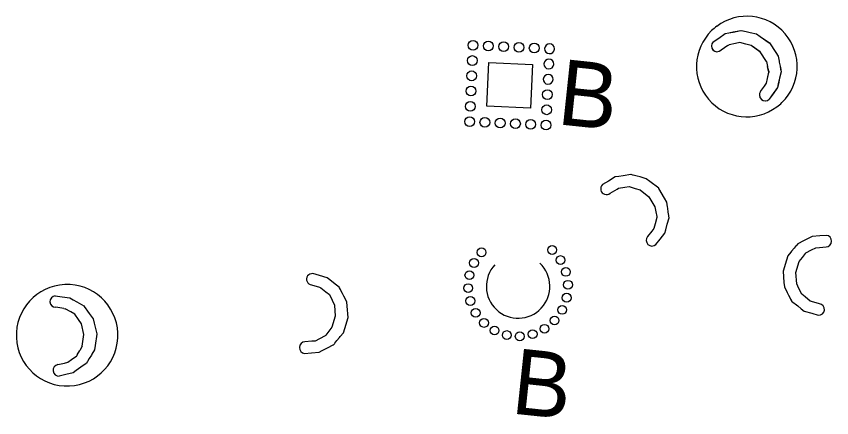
# Model space of a CAD drawing. Extents: x 2283629 to 2286552, y 529718 to 531440.
# Drawn here: x 2285323.2 to 2285509.6, y 530057 to 530148.9 of the extents above; entities that cross this region are included whole.
import ezdxf

# ---------------------------------------------------------------- set-up
doc = ezdxf.new("R2010")
doc.units = 0
for name, color, linetype in [('Draft_Corridor_Graphics_Design', 7, 'Continuous'), ('Draft_Corridor_Point_Control', 7, 'Continuous'), ('P_NCDOT_Terrain_Model_Contour_Major', 7, 'Continuous'), ('P_NCDOT_Terrain_Model_Triangles', 7, 'Continuous'), ('P_NCDOT_Terrain_Triangle_Vertices', 7, 'Continuous'), ('P_RDY_TC_Pvmt_Asphalt_Base_Course_Wedge', 7, 'Continuous'), ('P_RDY_TC_Pvmt_Asphalt_Surface_Course_Wedge', 7, 'Continuous')]:
    doc.layers.add(name, color=color, linetype=linetype)

msp = doc.modelspace()

# ---------------------------------------------------------------- linework, layer by layer
at = {"layer": 'Draft_Corridor_Point_Control'}
for p, q in [((2285446.23, 530141.4), (2285446.24, 530141.5)), ((2285446.08, 530137.91), (2285446.08, 530138)), ((2285445.92, 530134.42), (2285445.92, 530134.49))]:
    msp.add_line(p, q, dxfattribs=at)
msp.add_lwpolyline([(2285431.21, 530138.37), (2285441.2, 530137.91), (2285440.75, 530127.92), (2285430.76, 530128.39)], close=True, dxfattribs=at)
for centre in [(2285427.63, 530142.3), (2285431.13, 530142.14), (2285434.63, 530141.98), (2285438.12, 530141.82), (2285441.62, 530141.66), (2285427.47, 530138.8), (2285427.31, 530135.3), (2285427.16, 530131.81), (2285444.64, 530131.01), (2285427, 530128.31), (2285444.48, 530127.52), (2285426.84, 530124.81), (2285430.33, 530124.65), (2285433.83, 530124.5), (2285437.33, 530124.34), (2285440.82, 530124.18), (2285444.32, 530124.02)]:
    msp.add_circle(centre, 1.12, dxfattribs=at)
for centre, start, end in [((2285445.12, 530141.5), 359.9118, 354.8889), ((2285444.96, 530138), 359.5752, 355.2254), ((2285444.8, 530134.51), 359.1761, 355.6245)]:
    msp.add_arc(centre, 1.12, start, end, dxfattribs=at)
at = {"layer": 'P_NCDOT_Terrain_Model_Contour_Major'}
for p, q in [((2285485.88, 530142.23), (2285484.33, 530141.2)), ((2285485.89, 530142.22), (2285484.34, 530141.19)), ((2285485.88, 530142.23), (2285486.16, 530142.41)), ((2285485.89, 530142.22), (2285486.17, 530142.4)), ((2285487.61, 530142.7), (2285486.16, 530142.41)), ((2285487.62, 530142.7), (2285486.17, 530142.4)), ((2285488.62, 530142.91), (2285487.61, 530142.7)), ((2285488.63, 530142.9), (2285487.62, 530142.7)), ((2285490.02, 530142.56), (2285488.62, 530142.91)), ((2285490.03, 530142.55), (2285488.63, 530142.9)), ((2285491.19, 530142.27), (2285490.02, 530142.56)), ((2285491.2, 530142.26), (2285490.03, 530142.55)), ((2285493.24, 530140.77), (2285491.19, 530142.27)), ((2285493.25, 530140.77), (2285491.2, 530142.26)), ((2285493.24, 530140.77), (2285493.25, 530140.77)), ((2285493.25, 530140.77), (2285493.26, 530140.76)), ((2285494.73, 530138.59), (2285493.25, 530140.77)), ((2285494.74, 530138.58), (2285493.26, 530140.76)), ((2285494.73, 530138.59), (2285494.98, 530137.43)), ((2285494.74, 530138.58), (2285494.99, 530137.42)), ((2285494.96, 530134.69), (2285495.27, 530136.11)), ((2285494.97, 530134.68), (2285495.28, 530136.1)), ((2285495.22, 530136.34), (2285494.98, 530137.43)), ((2285495.23, 530136.33), (2285494.99, 530137.42)), ((2285495.22, 530136.34), (2285495.27, 530136.11)), ((2285495.23, 530136.33), (2285495.28, 530136.1)), ((2285494.73, 530133.61), (2285494.96, 530134.69)), ((2285494.73, 530133.61), (2285494.97, 530134.68)), ((2285493.36, 530131.71), (2285494.27, 530132.97)), ((2285493.37, 530131.7), (2285494.28, 530132.96)), ((2285494.27, 530132.97), (2285494.73, 530133.61)), ((2285494.28, 530132.96), (2285494.73, 530133.61))]:
    msp.add_line(p, q, dxfattribs=at)
for points in [[(2285482.52, 530143.06), (2285483.81, 530143.94), (2285485.31, 530144.97), (2285486.12, 530145.14), (2285487.11, 530145.34), (2285488.87, 530145.7), (2285488.91, 530145.69), (2285489.34, 530145.6), (2285489.42, 530145.58), (2285490.35, 530145.37), (2285491, 530145.23), (2285492.43, 530144.91), (2285493.28, 530144.31), (2285495.37, 530142.85), (2285495.38, 530142.84), (2285496.83, 530140.64), (2285497.4, 530139.78), (2285497.61, 530138.67), (2285497.66, 530138.43), (2285497.83, 530137.49), (2285497.97, 530136.77), (2285498, 530136.6), (2285498.07, 530136.24), (2285498.07, 530136.23), (2285497.73, 530134.76), (2285497.43, 530133.45), (2285497.25, 530132.66), (2285496.24, 530131.22), (2285495.36, 530129.95)], [(2285482.53, 530143.05), (2285483.81, 530143.93), (2285485.31, 530144.96), (2285486.13, 530145.13), (2285487.12, 530145.33), (2285488.88, 530145.69), (2285488.92, 530145.68), (2285489.35, 530145.59), (2285489.42, 530145.57), (2285490.36, 530145.36), (2285491.01, 530145.22), (2285492.44, 530144.9), (2285493.29, 530144.3), (2285495.38, 530142.84), (2285495.39, 530142.83), (2285496.84, 530140.63), (2285497.41, 530139.77), (2285497.62, 530138.66), (2285497.66, 530138.43), (2285497.84, 530137.48), (2285497.98, 530136.76), (2285498.01, 530136.59), (2285498.08, 530136.23), (2285498.08, 530136.23), (2285497.74, 530134.75), (2285497.44, 530133.45), (2285497.25, 530132.66), (2285496.25, 530131.21), (2285495.37, 530129.94)]]:
    msp.add_lwpolyline(points, dxfattribs=at)
for centre, radius, start, end in [((2285490.25, 530137.43), 11.5, 314.2425, 126.889), ((2285490.21, 530137.41), 11.5, 134.2425, 306.6479), ((2285490.21, 530137.41), 11.5, 126.6479, 134.2425), ((2285483.42, 530142.13), 1.3, 134.2425, 314.2425), ((2285483.43, 530142.12), 1.3, 134.2425, 314.2425), ((2285494.43, 530130.91), 1.33, 143.1299, 314.2425), ((2285494.44, 530130.9), 1.33, 143.1299, 314.2425), ((2285490.25, 530137.43), 11.5, 306.4067, 314.2425)]:
    msp.add_arc(centre, radius, start, end, dxfattribs=at)
at = {"layer": 'P_NCDOT_Terrain_Model_Triangles'}
for p, q in [((2285460.57, 530109.39), (2285460.86, 530109.56)), ((2285467.85, 530107.58), (2285467.86, 530107.57)), ((2285469.23, 530105.33), (2285469.43, 530104.16)), ((2285469.62, 530103.06), (2285469.65, 530102.83))]:
    msp.add_line(p, q, dxfattribs=at)
for points in [[(2285469.45, 530096.67), (2285470.39, 530097.9), (2285471.46, 530099.29), (2285471.68, 530100.07), (2285472.05, 530101.36), (2285472.46, 530102.82), (2285472.46, 530102.82), (2285472.4, 530103.19), (2285472.38, 530103.36), (2285472.28, 530104.08), (2285472.15, 530105.03), (2285472.12, 530105.27), (2285471.96, 530106.39), (2285471.43, 530107.27), (2285470.09, 530109.54), (2285470.08, 530109.55), (2285468.07, 530111.11), (2285467.24, 530111.75), (2285465.83, 530112.14), (2285465.19, 530112.32), (2285464.27, 530112.57), (2285464.19, 530112.59), (2285463.77, 530112.71), (2285463.73, 530112.72), (2285461.96, 530112.44), (2285460.96, 530112.28), (2285460.13, 530112.15), (2285458.58, 530111.2), (2285457.25, 530110.39)], [(2285458.97, 530108.44), (2285460.57, 530109.39), (2285460.86, 530109.56), (2285462.32, 530109.78), (2285463.34, 530109.94), (2285464.72, 530109.53), (2285465.88, 530109.18), (2285467.85, 530107.58), (2285467.86, 530107.57), (2285469.23, 530105.33), (2285469.43, 530104.16), (2285469.62, 530103.06), (2285469.65, 530102.83), (2285469.28, 530101.43), (2285468.99, 530100.36), (2285468.5, 530099.74), (2285467.54, 530098.52), (2285467.54, 530098.52)]]:
    msp.add_lwpolyline(points, dxfattribs=at)
for centre, radius, start in [((2285458.11, 530109.41), 1.3, 131.4705), ((2285468.56, 530097.67), 1.33, 140.3579)]:
    msp.add_arc(centre, radius, start, 311.4705, dxfattribs=at)
at = {"layer": 'P_NCDOT_Terrain_Triangle_Vertices'}
for p, q in [((2285334.07, 530082.04), (2285332.23, 530082.3)), ((2285334.07, 530082.04), (2285334.4, 530081.99)), ((2285335.68, 530081.25), (2285334.4, 530081.99)), ((2285336.57, 530080.73), (2285335.68, 530081.25)), ((2285337.39, 530079.54), (2285336.57, 530080.73)), ((2285338.07, 530078.55), (2285337.39, 530079.54)), ((2285338.61, 530076.06), (2285338.07, 530078.55)), ((2285338.27, 530073.44), (2285338.61, 530076.05)), ((2285338.61, 530076.06), (2285338.61, 530076.05)), ((2285337.14, 530071.44), (2285337.69, 530072.4)), ((2285338.27, 530073.44), (2285337.69, 530072.4)), ((2285335.85, 530070.38), (2285337.03, 530071.23)), ((2285337.14, 530071.44), (2285337.03, 530071.23)), ((2285332.68, 530069.21), (2285334.19, 530069.55)), ((2285334.19, 530069.55), (2285334.96, 530069.73)), ((2285334.96, 530069.73), (2285335.85, 530070.38))]:
    msp.add_line(p, q, dxfattribs=at)
msp.add_lwpolyline([(2285332.11, 530084.9), (2285333.66, 530084.7), (2285335.46, 530084.47), (2285336.19, 530084.05), (2285337.06, 530083.55), (2285338.62, 530082.65), (2285338.64, 530082.62), (2285338.9, 530082.26), (2285338.94, 530082.2), (2285339.5, 530081.42), (2285339.89, 530080.88), (2285340.75, 530079.69), (2285340.99, 530078.68), (2285341.58, 530076.2), (2285341.58, 530076.19), (2285341.2, 530073.58), (2285341.06, 530072.56), (2285340.47, 530071.59), (2285340.35, 530071.38), (2285339.86, 530070.56), (2285339.48, 530069.93), (2285339.39, 530069.79), (2285339.21, 530069.47), (2285339.2, 530069.46), (2285337.97, 530068.59), (2285336.87, 530067.81), (2285336.21, 530067.34), (2285334.51, 530066.93), (2285333, 530066.57)], dxfattribs=at)
for centre, radius, start, end in [((2285334.81, 530075.91), 11.62, 92.6069, 182.6069), ((2285334.81, 530075.91), 11.62, 2.6069, 92.6069), ((2285332.17, 530083.6), 1.3, 92.6069, 272.6069), ((2285334.81, 530075.91), 11.62, 272.6069, 2.6069), ((2285334.81, 530075.91), 11.62, 182.6069, 272.6069), ((2285332.94, 530067.9), 1.33, 101.4943, 272.6069)]:
    msp.add_arc(centre, radius, start, end, dxfattribs=at)
at = {"layer": 'P_RDY_TC_Pvmt_Asphalt_Base_Course_Wedge'}
for p, q in [((2285503.62, 530094.59), (2285503.76, 530094.78)), ((2285502.2, 530092.78), (2285502.93, 530093.72)), ((2285501.47, 530090.24), (2285501.47, 530090.25)), ((2285392.51, 530086.89), (2285392.82, 530086.79)), ((2285505.05, 530083.65), (2285504.74, 530083.74)), ((2285396.09, 530080.3), (2285396.09, 530080.29)), ((2285395.36, 530077.76), (2285394.63, 530076.82)), ((2285393.94, 530075.94), (2285393.8, 530075.76))]:
    msp.add_line(p, q, dxfattribs=at)
for points in [[(2285508.44, 530098.78), (2285506.9, 530098.65), (2285505.15, 530098.5), (2285504.43, 530098.13), (2285503.23, 530097.53), (2285501.88, 530096.85), (2285501.87, 530096.85), (2285501.64, 530096.56), (2285501.53, 530096.43), (2285501.07, 530095.87), (2285500.45, 530095.13), (2285500.3, 530094.94), (2285499.58, 530094.07), (2285499.28, 530093.09), (2285498.52, 530090.56), (2285498.52, 530090.55), (2285498.72, 530088.01), (2285498.81, 530086.97), (2285499.48, 530085.67), (2285499.78, 530085.07), (2285500.22, 530084.22), (2285500.25, 530084.16), (2285500.45, 530083.76), (2285500.47, 530083.73), (2285501.87, 530082.61), (2285502.66, 530081.97), (2285503.32, 530081.45), (2285505.06, 530080.95), (2285506.56, 530080.53)], [(2285506.84, 530083.11), (2285505.05, 530083.65), (2285504.74, 530083.74), (2285503.58, 530084.67), (2285502.78, 530085.32), (2285502.15, 530086.62), (2285501.63, 530087.7), (2285501.47, 530090.24), (2285501.47, 530090.25), (2285502.2, 530092.78), (2285502.93, 530093.72), (2285503.62, 530094.59), (2285503.76, 530094.78), (2285505.05, 530095.45), (2285506.03, 530095.95), (2285506.82, 530096.01), (2285508.37, 530096.12), (2285508.37, 530096.12)], [(2285389.12, 530071.75), (2285390.66, 530071.89), (2285392.41, 530072.04), (2285393.13, 530072.4), (2285394.33, 530073.01), (2285395.68, 530073.69), (2285395.69, 530073.69), (2285395.92, 530073.97), (2285396.03, 530074.11), (2285396.5, 530074.67), (2285397.11, 530075.41), (2285397.26, 530075.59), (2285397.98, 530076.46), (2285398.28, 530077.45), (2285399.04, 530079.97), (2285399.04, 530079.99), (2285398.84, 530082.53), (2285398.75, 530083.56), (2285398.08, 530084.87), (2285397.78, 530085.46), (2285397.34, 530086.31), (2285397.31, 530086.38), (2285397.11, 530086.77), (2285397.09, 530086.81), (2285395.69, 530087.93), (2285394.9, 530088.56), (2285394.24, 530089.08), (2285392.5, 530089.58), (2285391, 530090.01)], [(2285390.72, 530087.43), (2285392.51, 530086.89), (2285392.82, 530086.79), (2285393.98, 530085.86), (2285394.78, 530085.22), (2285395.41, 530083.92), (2285395.93, 530082.83), (2285396.09, 530080.3), (2285396.09, 530080.29), (2285395.36, 530077.76), (2285394.63, 530076.82), (2285393.94, 530075.94), (2285393.8, 530075.76), (2285392.51, 530075.09), (2285391.53, 530074.58), (2285390.74, 530074.52), (2285389.19, 530074.41), (2285389.19, 530074.41)]]:
    msp.add_lwpolyline(points, dxfattribs=at)
for centre, radius, start, end in [((2285508.3, 530097.46), 1.33, 272.8376, 83.9503), ((2285390.86, 530088.72), 1.3, 83.9503, 263.9503), ((2285506.7, 530081.82), 1.3, 263.9503, 83.9503), ((2285389.26, 530073.08), 1.33, 92.8376, 263.9503)]:
    msp.add_arc(centre, radius, start, end, dxfattribs=at)
at = {"layer": 'P_RDY_TC_Pvmt_Asphalt_Surface_Course_Wedge'}
for centre in [(2285429.58, 530094.88), (2285445.73, 530095.43), (2285427.85, 530092.46), (2285447.62, 530093.12), (2285448.86, 530090.41), (2285426.8, 530089.66), (2285426.51, 530086.7), (2285449.34, 530087.47), (2285449.05, 530084.5), (2285427, 530083.75), (2285428.23, 530081.04), (2285448.01, 530081.71), (2285446.27, 530079.28), (2285430.13, 530078.73), (2285432.55, 530077), (2285443.97, 530077.39), (2285435.34, 530075.95), (2285438.31, 530075.66), (2285441.25, 530076.15)]:
    msp.add_circle(centre, 1.01, dxfattribs=at)
msp.add_arc((2285437.93, 530087.08), 7.26, 136.9409, 46.9321, dxfattribs=at)

# ---------------------------------------------------------------- texts
at = {"layer": 'Draft_Corridor_Graphics_Design'}
for p in [(2285446.6, 530124.25), (2285436.06, 530058.04)]:
    msp.add_text('B', height=15, rotation=353.9503, dxfattribs=at).set_placement(p)

doc.saveas('drawing.dxf')
